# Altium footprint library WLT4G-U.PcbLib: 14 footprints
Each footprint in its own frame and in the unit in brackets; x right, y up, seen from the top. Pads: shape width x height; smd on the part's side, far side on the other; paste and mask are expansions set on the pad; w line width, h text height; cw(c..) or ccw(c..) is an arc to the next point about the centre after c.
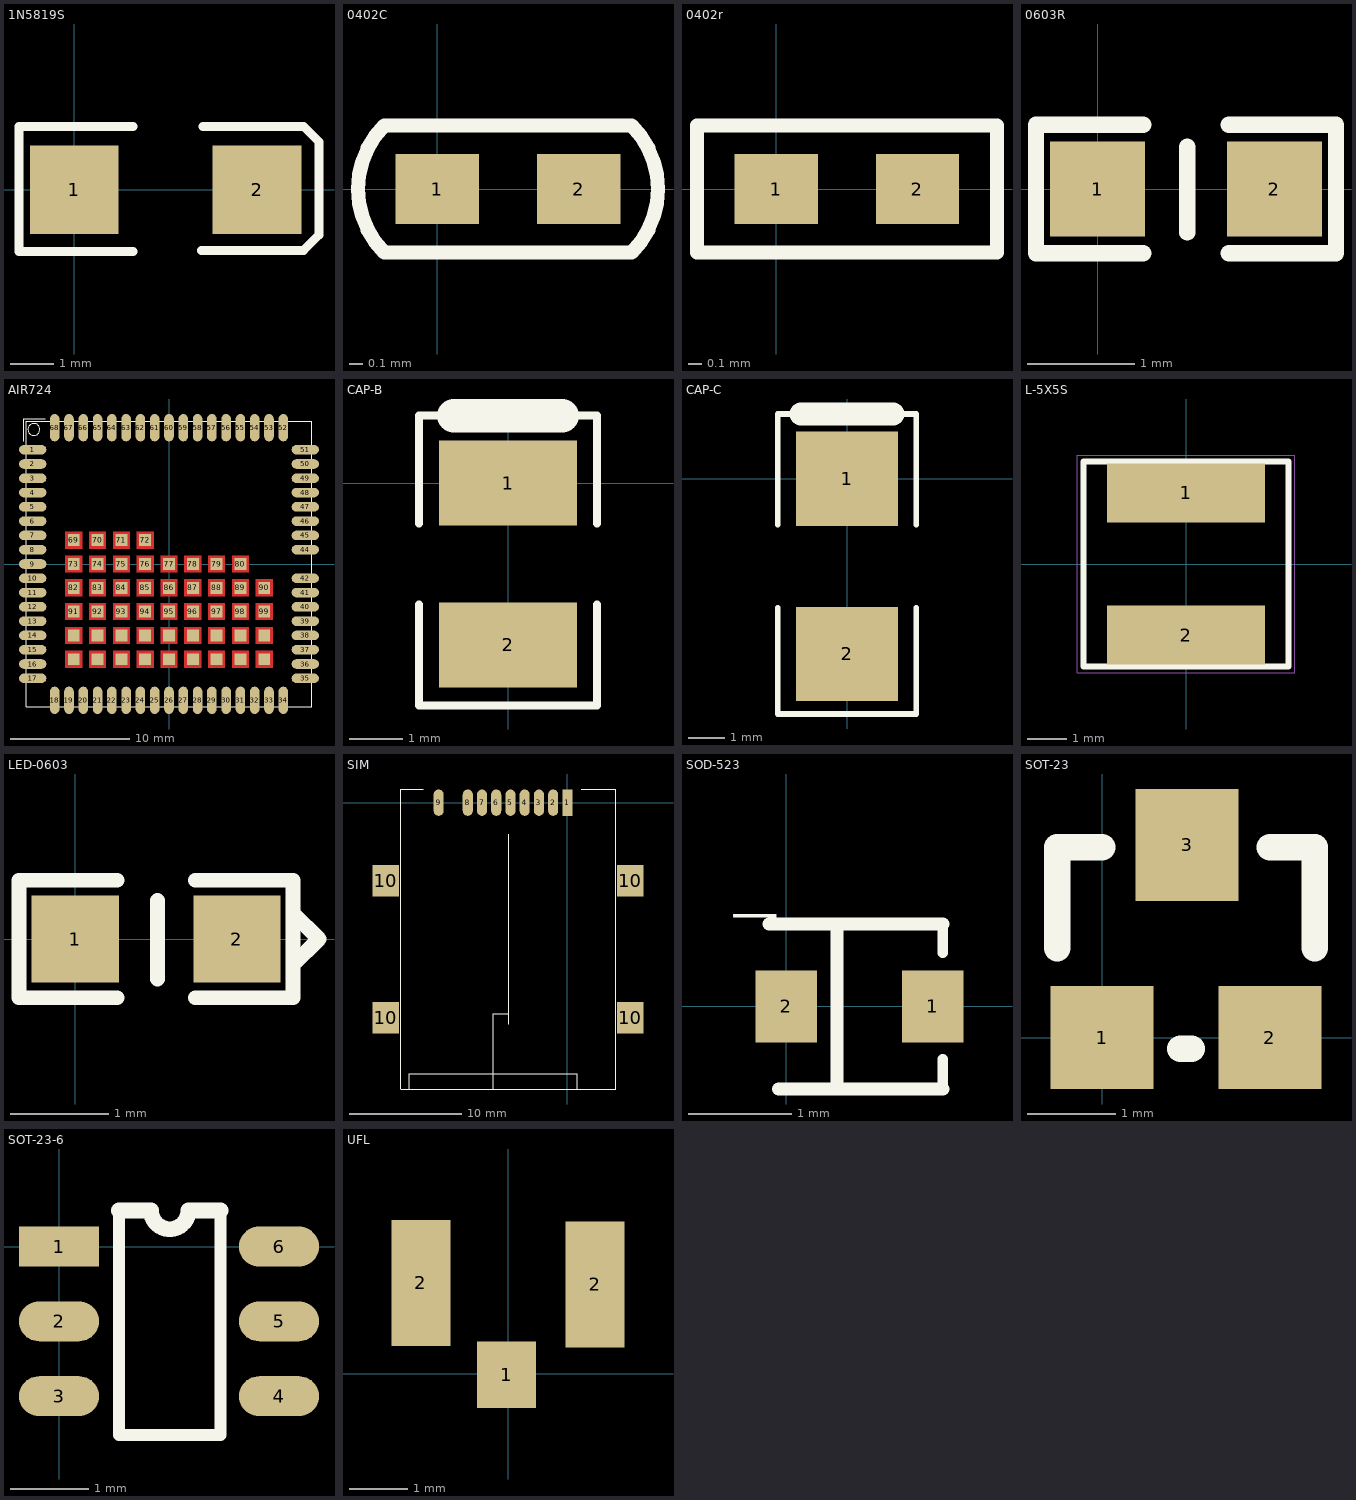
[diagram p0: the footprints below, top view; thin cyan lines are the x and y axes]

## 1N5819S [mil]
height 180
pads (2):
  rect 80x80 smd: 1(0,0) 2(165,0)
Top Overlay:
  lines w8: 53,-56 -50,-56 -50,57 53,57 ; 115,-55 207,-55 221,-41 221,43 207,57 116,57

## 0402C [mm]
height 0.635
pads (2):
  rect 0.6x0.5 smd: 1(0,0) 2(1.016,0)
Top Overlay:
  lines w0.102: -0.381,-0.457 cw(c0.076,0) -0.381,0.457 1.397,0.457 cw(c0.94,0) 1.397,-0.457 -0.381,-0.457

## 0402r [mm]
height 0.635
pads (2):
  rect 0.6x0.5 smd: 1(0,0) 2(1.016,0)
Top Overlay:
  lines w0.102: -0.381,-0.457 1.397,-0.457 ; 1.194,0.457 1.587,0.457 1.587,-0.457 -0.569,-0.457 -0.569,0.457 -0.381,0.457 1.397,0.457

## 0603R [mil]
height 180
pads (2):
  rect 35x35 smd: 1(0,0) 2(65,0)
Top Overlay:
  lines w6: 16.75,-23.62 -22.62,-23.62 -22.62,23.62 16.75,23.62 ; 33,-16 33,15.5 ; 48.24,-23.62 87.61,-23.62 87.61,23.62 48.24,23.62

## AIR724 [mm]
height 8.636
pads (115):
  oval 2.3x0.8 smd: 1(-11.45,9.6) 2(-11.45,8.4) 3(-11.45,7.2) 4(-11.45,6) 5(-11.45,4.8) 6(-11.45,3.6) 7(-11.45,2.4) 8(-11.45,1.2) 9(-11.45,0) 10(-11.45,-1.2) 11(-11.45,-2.4) 12(-11.45,-3.6) 13(-11.45,-4.8) 14(-11.45,-6) 15(-11.45,-7.2) 16(-11.45,-8.4) 17(-11.45,-9.6) 35(11.45,-9.6) 36(11.45,-8.4) 37(11.45,-7.2) 38(11.45,-6) 39(11.45,-4.8) 40(11.45,-3.6) 41(11.45,-2.4) 42(11.45,-1.2) 44(11.45,1.2) 45(11.45,2.4) 46(11.45,3.6) 47(11.45,4.8) 48(11.45,6) 49(11.45,7.2) 50(11.45,8.4) 51(11.45,9.6)
  oval 0.8x2.3 smd: 18(-9.6,-11.45) 19(-8.4,-11.45) 20(-7.2,-11.45) 21(-6,-11.45) 22(-4.8,-11.45) 23(-3.6,-11.45) 24(-2.4,-11.45) 25(-1.2,-11.45) 26(0,-11.45) 27(1.2,-11.45) 28(2.4,-11.45) 29(3.6,-11.45) 30(4.8,-11.45) 31(6,-11.45) 32(7.2,-11.45) 33(8.4,-11.45) 34(9.6,-11.45) 52(9.6,11.45) 53(8.4,11.45) 54(7.2,11.45) 55(6,11.45) 56(4.8,11.45) 57(3.6,11.45) 58(2.4,11.45) 59(1.2,11.45) 60(0,11.45) 61(-1.2,11.45) 62(-2.4,11.45) 63(-3.6,11.45) 64(-4.8,11.45) 65(-6,11.45) 66(-7.2,11.45) 67(-8.4,11.45) 68(-9.6,11.45)
  rect 1x1 smd: 69(-8,2) 70(-6,2) 71(-4,2) 72(-2,2) 73(-8,0) 74(-6,0) 75(-4,0) 76(-2,0) 77(0,0) 78(2,0) 79(4,0) 80(6,0) 82(-8,-2) 83(-6,-2) 84(-4,-2) 85(-2,-2) 86(0,-2) 87(2,-2) 88(4,-2) 89(6,-2) 90(8,-2) 91(-8,-4) 92(-6,-4) 93(-4,-4) 94(-2,-4) 95(0,-4) 96(2,-4) 97(4,-4) 98(6,-4) 99(8,-4) 100(-8,-6) 101(-6,-6) 102(-4,-6) 103(-2,-6) 104(0,-6) 105(2,-6) 106(4,-6) 107(6,-6) 108(8,-6) 109(-8,-8) 110(-6,-8) 111(-4,-8) 112(-2,-8) 113(0,-8) 114(2,-8) 115(4,-8) 116(6,-8) 117(8,-8)
Top Layer:
  region: 7.3,-3.3 8.7,-3.3 8.7,-4.7 7.3,-4.7
  region: -8.7,-7.3 -7.3,-7.3 -7.3,-8.7 -8.7,-8.7
  region: -8.7,-5.3 -7.3,-5.3 -7.3,-6.7 -8.7,-6.7
  region: 7.3,-7.3 8.7,-7.3 8.7,-8.7 7.3,-8.7
  region: 7.3,-5.3 8.7,-5.3 8.7,-6.7 7.3,-6.7
  region: 5.3,-7.3 6.7,-7.3 6.7,-8.7 5.3,-8.7
  region: 5.3,-5.3 6.7,-5.3 6.7,-6.7 5.3,-6.7
  region: 7.3,-1.3 8.7,-1.3 8.7,-2.7 7.3,-2.7
  region: 5.3,-1.3 6.7,-1.3 6.7,-2.7 5.3,-2.7
  region: 5.3,0.7 6.7,0.7 6.7,-0.7 5.3,-0.7
  region: 3.3,-1.3 4.7,-1.3 4.7,-2.7 3.3,-2.7
  region: 3.3,0.7 4.7,0.7 4.7,-0.7 3.3,-0.7
  region: 1.3,-1.3 2.7,-1.3 2.7,-2.7 1.3,-2.7
  region: 1.3,0.7 2.7,0.7 2.7,-0.7 1.3,-0.7
  region: -0.7,-1.3 0.7,-1.3 0.7,-2.7 -0.7,-2.7
  region: -0.7,0.7 0.7,0.7 0.7,-0.7 -0.7,-0.7
  region: -8.7,2.7 -7.3,2.7 -7.3,1.3 -8.7,1.3
  region: -8.7,0.7 -7.3,0.7 -7.3,-0.7 -8.7,-0.7
  region: -6.7,2.7 -5.3,2.7 -5.3,1.3 -6.7,1.3
  region: -6.7,0.7 -5.3,0.7 -5.3,-0.7 -6.7,-0.7
  region: -4.7,2.7 -3.3,2.7 -3.3,1.3 -4.7,1.3
  region: -4.7,0.7 -3.3,0.7 -3.3,-0.7 -4.7,-0.7
  region: -8.7,-3.3 -7.3,-3.3 -7.3,-4.7 -8.7,-4.7
  region: -6.7,-3.3 -5.3,-3.3 -5.3,-4.7 -6.7,-4.7
  region: -4.7,-3.3 -3.3,-3.3 -3.3,-4.7 -4.7,-4.7
  region: -8.7,-1.3 -7.3,-1.3 -7.3,-2.7 -8.7,-2.7
  region: -6.7,-1.3 -5.3,-1.3 -5.3,-2.7 -6.7,-2.7
  region: -4.7,-1.3 -3.3,-1.3 -3.3,-2.7 -4.7,-2.7
  region: 5.3,-3.3 6.7,-3.3 6.7,-4.7 5.3,-4.7
  region: 3.3,-3.3 4.7,-3.3 4.7,-4.7 3.3,-4.7
  region: 1.3,-3.3 2.7,-3.3 2.7,-4.7 1.3,-4.7
  region: -0.7,-3.3 0.7,-3.3 0.7,-4.7 -0.7,-4.7
  region: -2.7,2.7 -1.3,2.7 -1.3,1.3 -2.7,1.3
  region: -2.7,0.7 -1.3,0.7 -1.3,-0.7 -2.7,-0.7
  region: -2.7,-1.3 -1.3,-1.3 -1.3,-2.7 -2.7,-2.7
  region: -2.7,-3.3 -1.3,-3.3 -1.3,-4.7 -2.7,-4.7
  region: -6.7,-7.3 -5.3,-7.3 -5.3,-8.7 -6.7,-8.7
  region: -4.7,-7.3 -3.3,-7.3 -3.3,-8.7 -4.7,-8.7
  region: -2.7,-7.3 -1.3,-7.3 -1.3,-8.7 -2.7,-8.7
  region: -0.7,-7.3 0.7,-7.3 0.7,-8.7 -0.7,-8.7
  region: 1.3,-7.3 2.7,-7.3 2.7,-8.7 1.3,-8.7
  region: 3.3,-7.3 4.7,-7.3 4.7,-8.7 3.3,-8.7
  region: 3.3,-5.3 4.7,-5.3 4.7,-6.7 3.3,-6.7
  region: 1.3,-5.3 2.7,-5.3 2.7,-6.7 1.3,-6.7
  region: -0.7,-5.3 0.7,-5.3 0.7,-6.7 -0.7,-6.7
  region: -2.7,-5.3 -1.3,-5.3 -1.3,-6.7 -2.7,-6.7
  region: -4.7,-5.3 -3.3,-5.3 -3.3,-6.7 -4.7,-6.7
  region: -6.7,-5.3 -5.3,-5.3 -5.3,-6.7 -6.7,-6.7
Top Overlay:
  circle w0.1: c-11.35,11.3 r0.5
  lines w0.1: -12.2,10.3 -12.2,12.2 -10.4,12.2 ; -12,-12 -12,12 12,12 12,-12 -12,-12

## CAP-B [mm]
height 4.572
pads (2):
  rect 2.6x1.6 smd: 1(0,0) 2(0,-3.048)
Top Overlay:
  lines w0.152: -1.676,-2.286 -1.676,-4.191 1.676,-4.191 1.676,-2.286 ; -1.676,-0.762 -1.676,1.27 1.676,1.27 1.676,-0.762
  lines w0.635: -1.016,1.27 1.016,1.27

## CAP-C [mm]
pads (2):
  rect 2.8x2.6 smd: 1(0,0) 2(0,-4.826)
Top Overlay:
  lines w0.152: -1.905,-3.556 -1.905,-6.477 1.905,-6.477 1.905,-3.556 ; -1.905,-1.27 -1.905,1.778 1.905,1.778 1.905,-1.27
  lines w0.635: -1.27,1.778 1.27,1.778

## L-5X5S [mm]
pads (2):
  rect 4x1.5 smd: 1(0,1.8) 2(0,-1.8)
Top Overlay:
  lines w0.15: -2.6,-2.6 -2.6,2.6 2.6,2.6 2.6,-2.6 -2.6,-2.6
Mechanical 1:
  lines w0.025: -2.75,-2.75 -2.75,2.75 2.75,2.75 2.75,-2.75 -2.75,-2.75

## LED-0603 [mil] "20100324  贴片0603LED   LSB"
height 35
pads (2):
  rect 35x35 smd: 1(0,0) 2(65,0)
Top Overlay:
  lines w6: 16.75,-23.62 -22.62,-23.62 -22.62,23.62 16.75,23.62 ; 33,-16 33,15.5 ; 48.24,-23.62 87.61,-23.62 87.61,23.62 48.24,23.62 ; 87.61,-10.39 98,0 87.61,10.39

## SIM [mm]
height 0.35
pads (13):
  rect 0.9x2.35 smd: 1(0,0)
  oval 0.9x2.35 smd: 2(-1.27,0) 3(-2.54,0) 4(-3.81,0) 5(-5.08,0) 6(-6.35,0) 7(-7.62,0) 8(-8.89,0) 9(-11.49,0)
  rect 2.35x2.8 smd: 10(-16.2,-19.2) 10(-16.2,-6.95) 10(5.6,-19.2) 10(5.6,-6.95)
Top Overlay:
  lines w0.1: -14.85,-19.075 -14.85,-2.4 ; -14.85,-17.95 -14.85,-25.55 -14.85,-7.05 ; -14.85,-3.3 -14.85,1.225 -12.85,1.225 ; -14.825,-25.55 -5.075,-25.55 ; -14.1,-25.55 -14.1,-24.2 -6.6,-24.2 0.9,-24.2 0.9,-25.55 ; -6.675,-25.55 4.325,-25.55 4.325,1.2 ; -6.6,-25.525 -6.6,-18.825 -5.25,-18.825 ; -5.25,-19.775 -5.25,-2.825 ; 1.25,1.2 4.325,1.2 ; 4.325,-18.075 4.325,-3.3 4.325,1.2

## SOD-523 [mm]
height 0.965
pads (2):
  rect 0.6x0.7 smd: 1(1.42,0) 2(0,0)
Top Overlay:
  lines w0.102: 1.517,-0.8 1.517,-0.509 ; 1.517,0.522 1.517,0.8
  lines w0.127: -0.166,0.8 1.517,0.8 ; -0.073,-0.8 1.517,-0.8 ; 0.49,-0.8 0.49,0.8
  text "-" at -0.593,0.109 h2

## SOT-23 [mil]
height 180
pads (3):
  rect 46x46 smd: 1(0,0) 2(75,0)
  rect 46x50 smd: 3(38,86)
Top Overlay:
  lines w12: -20,40 -20,85 0,85 ; 35,-5 40,-5 ; 75,85 95,85 95,40

## SOT-23-6 [mil]
pads (6):
  rect 40x20 smd: 1(0,0)
  oval 40x20 smd: 2(0,-37.4) 3(0,-74.8) 4(110,-74.8) 5(110,-37.4) 6(110,0)
Top Overlay:
  lines w6: 30,18 30,-94.2 80.7,-94.2 80.7,18
  lines w7.87: 46,18 ccw(c55.35,18) 64.7,18
  lines w8: 30,18 46,18 ; 64.7,18 80.7,18

## UFL [mil]
height 180
pads (3):
  rect 40x45 smd: 1(-1.15,-0.54)
  rect 40x85 smd: 2(-59.15,61.46) 2(58.85,60.46)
